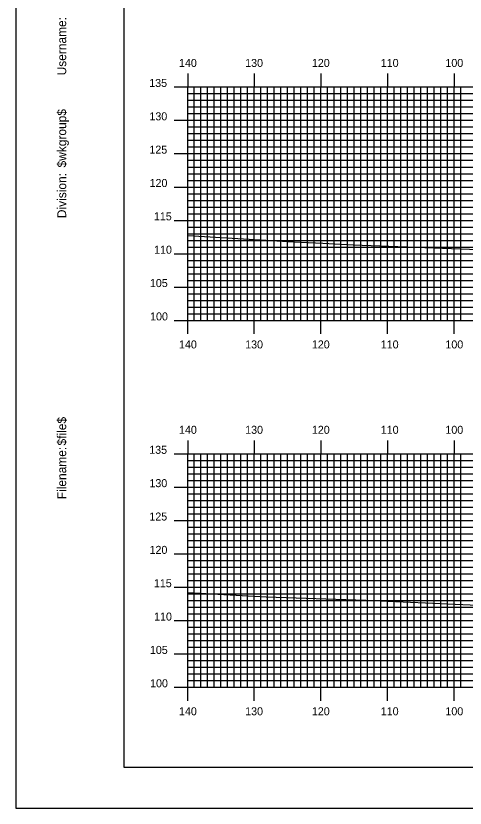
# Model space of a CAD drawing. Extents: x 1781467 to 1781810, y 442591 to 442811.
# Drawn here: x 1781466.6 to 1781534.1, y 442590.5 to 442709.3 of the extents above; entities that cross this region are included whole.
import ezdxf

# ---------------------------------------------------------------- set-up
doc = ezdxf.new("R2010")
doc.units = 0
for name, color, linetype in [('BORDER', 7, 'Continuous'), ('H_V ANNOTATION', 7, 'Continuous'), ('MAJOR', 7, 'Continuous'), ('MINOR', 7, 'Continuous'), ('PLOT BOUNDARY', 7, 'Continuous'), ('S_Roadway_Centerline', 7, 'Continuous')]:
    doc.layers.add(name, color=color, linetype=linetype)

msp = doc.modelspace()

# ---------------------------------------------------------------- linework, layer by layer
at = {"layer": 'BORDER'}
msp.add_lwpolyline([(1781482.81, 442596.67), (1781802.81, 442596.67), (1781802.81, 442806.67), (1781482.81, 442806.67)], close=True, dxfattribs=at)
at = {"layer": 'MAJOR'}
for p, q in [((1781492.41, 442700.67), (1781492.41, 442698.67)), ((1781502.41, 442700.67), (1781502.41, 442698.67)), ((1781512.41, 442700.67), (1781512.41, 442698.67)), ((1781522.41, 442700.67), (1781522.41, 442698.67)), ((1781532.41, 442700.67), (1781532.41, 442698.67)), ((1781490.4, 442698.67), (1781492.41, 442698.67)), ((1781492.41, 442698.67), (1781772.41, 442698.67)), ((1781492.41, 442663.67), (1781492.41, 442698.67)), ((1781492.41, 442663.67), (1781492.41, 442698.67)), ((1781492.41, 442698.67), (1781772.41, 442698.67)), ((1781502.41, 442663.67), (1781502.41, 442698.67)), ((1781512.41, 442663.67), (1781512.41, 442698.67)), ((1781522.41, 442663.67), (1781522.41, 442698.67)), ((1781532.41, 442663.67), (1781532.41, 442698.67)), ((1781490.4, 442693.67), (1781492.41, 442693.67)), ((1781492.41, 442693.67), (1781772.41, 442693.67)), ((1781490.4, 442688.67), (1781492.41, 442688.67)), ((1781492.41, 442688.67), (1781772.41, 442688.67)), ((1781490.4, 442683.67), (1781492.41, 442683.67)), ((1781492.41, 442683.67), (1781772.41, 442683.67)), ((1781490.4, 442678.67), (1781492.41, 442678.67)), ((1781492.41, 442678.67), (1781772.41, 442678.67)), ((1781490.4, 442673.67), (1781492.41, 442673.67)), ((1781492.41, 442673.67), (1781772.41, 442673.67)), ((1781490.4, 442668.67), (1781492.41, 442668.67)), ((1781492.41, 442668.67), (1781772.41, 442668.67)), ((1781490.4, 442663.67), (1781492.41, 442663.67)), ((1781492.41, 442663.67), (1781772.41, 442663.67)), ((1781492.41, 442663.67), (1781772.41, 442663.67)), ((1781492.41, 442661.66), (1781492.41, 442663.67)), ((1781502.41, 442661.66), (1781502.41, 442663.67)), ((1781512.41, 442661.66), (1781512.41, 442663.67)), ((1781522.41, 442661.66), (1781522.41, 442663.67)), ((1781532.41, 442661.66), (1781532.41, 442663.67)), ((1781492.41, 442645.67), (1781492.41, 442643.67)), ((1781502.41, 442645.67), (1781502.41, 442643.67)), ((1781512.41, 442645.67), (1781512.41, 442643.67)), ((1781522.41, 442645.67), (1781522.41, 442643.67)), ((1781532.41, 442645.67), (1781532.41, 442643.67)), ((1781490.4, 442643.67), (1781492.41, 442643.67)), ((1781492.41, 442643.67), (1781772.41, 442643.67)), ((1781492.41, 442608.67), (1781492.41, 442643.67)), ((1781492.41, 442608.67), (1781492.41, 442643.67)), ((1781492.41, 442643.67), (1781772.41, 442643.67)), ((1781502.41, 442608.67), (1781502.41, 442643.67)), ((1781512.41, 442608.67), (1781512.41, 442643.67)), ((1781522.41, 442608.67), (1781522.41, 442643.67)), ((1781532.41, 442608.67), (1781532.41, 442643.67)), ((1781490.4, 442638.67), (1781492.41, 442638.67)), ((1781492.41, 442638.67), (1781772.41, 442638.67)), ((1781490.4, 442633.67), (1781492.41, 442633.67)), ((1781492.41, 442633.67), (1781772.41, 442633.67)), ((1781490.4, 442628.67), (1781492.41, 442628.67)), ((1781492.41, 442628.67), (1781772.41, 442628.67)), ((1781490.4, 442623.67), (1781492.41, 442623.67)), ((1781492.41, 442623.67), (1781772.41, 442623.67)), ((1781490.4, 442618.67), (1781492.41, 442618.67)), ((1781492.41, 442618.67), (1781772.41, 442618.67)), ((1781490.4, 442613.67), (1781492.41, 442613.67)), ((1781492.41, 442613.67), (1781772.41, 442613.67)), ((1781490.4, 442608.67), (1781492.41, 442608.67)), ((1781492.41, 442608.67), (1781772.41, 442608.67)), ((1781492.41, 442608.67), (1781772.41, 442608.67)), ((1781492.41, 442606.66), (1781492.41, 442608.67)), ((1781502.41, 442606.66), (1781502.41, 442608.67)), ((1781512.41, 442606.66), (1781512.41, 442608.67)), ((1781522.41, 442606.66), (1781522.41, 442608.67)), ((1781532.41, 442606.66), (1781532.41, 442608.67))]:
    msp.add_line(p, q, dxfattribs=at)
at = {"layer": 'MINOR'}
for p, q in [((1781493.41, 442663.67), (1781493.41, 442698.67)), ((1781494.41, 442663.67), (1781494.41, 442698.67)), ((1781495.41, 442663.67), (1781495.41, 442698.67)), ((1781496.41, 442663.67), (1781496.41, 442698.67)), ((1781497.41, 442663.67), (1781497.41, 442698.67)), ((1781498.41, 442663.67), (1781498.41, 442698.67)), ((1781499.41, 442663.67), (1781499.41, 442698.67)), ((1781500.41, 442663.67), (1781500.41, 442698.67)), ((1781501.41, 442663.67), (1781501.41, 442698.67)), ((1781503.41, 442663.67), (1781503.41, 442698.67)), ((1781504.41, 442663.67), (1781504.41, 442698.67)), ((1781505.41, 442663.67), (1781505.41, 442698.67)), ((1781506.41, 442663.67), (1781506.41, 442698.67)), ((1781507.41, 442663.67), (1781507.41, 442698.67)), ((1781508.41, 442663.67), (1781508.41, 442698.67)), ((1781509.41, 442663.67), (1781509.41, 442698.67)), ((1781510.41, 442663.67), (1781510.41, 442698.67)), ((1781511.41, 442663.67), (1781511.41, 442698.67)), ((1781513.41, 442663.67), (1781513.41, 442698.67)), ((1781514.41, 442663.67), (1781514.41, 442698.67)), ((1781515.41, 442663.67), (1781515.41, 442698.67)), ((1781516.41, 442663.67), (1781516.41, 442698.67)), ((1781517.41, 442663.67), (1781517.41, 442698.67)), ((1781518.41, 442663.67), (1781518.41, 442698.67)), ((1781519.41, 442663.67), (1781519.41, 442698.67)), ((1781520.41, 442663.67), (1781520.41, 442698.67)), ((1781521.41, 442663.67), (1781521.41, 442698.67)), ((1781523.41, 442663.67), (1781523.41, 442698.67)), ((1781524.41, 442663.67), (1781524.41, 442698.67)), ((1781525.41, 442663.67), (1781525.41, 442698.67)), ((1781526.41, 442663.67), (1781526.41, 442698.67)), ((1781527.41, 442663.67), (1781527.41, 442698.67)), ((1781528.41, 442663.67), (1781528.41, 442698.67)), ((1781529.41, 442663.67), (1781529.41, 442698.67)), ((1781530.41, 442663.67), (1781530.41, 442698.67)), ((1781531.41, 442663.67), (1781531.41, 442698.67)), ((1781533.41, 442663.67), (1781533.41, 442698.67)), ((1781492.41, 442697.67), (1781772.41, 442697.67)), ((1781492.41, 442697.67), (1781494.41, 442697.67)), ((1781492.41, 442696.67), (1781772.41, 442696.67)), ((1781492.41, 442696.67), (1781494.41, 442696.67)), ((1781492.41, 442695.67), (1781772.41, 442695.67)), ((1781492.41, 442695.67), (1781494.41, 442695.67)), ((1781492.41, 442694.67), (1781772.41, 442694.67)), ((1781492.41, 442694.67), (1781494.41, 442694.67)), ((1781492.41, 442692.67), (1781772.41, 442692.67)), ((1781492.41, 442692.67), (1781494.41, 442692.67)), ((1781492.41, 442691.67), (1781772.41, 442691.67)), ((1781492.41, 442691.67), (1781494.41, 442691.67)), ((1781492.41, 442690.67), (1781772.41, 442690.67)), ((1781492.41, 442690.67), (1781494.41, 442690.67)), ((1781492.41, 442689.67), (1781772.41, 442689.67)), ((1781492.41, 442689.67), (1781494.41, 442689.67)), ((1781492.41, 442687.67), (1781772.41, 442687.67)), ((1781492.41, 442687.67), (1781494.41, 442687.67)), ((1781492.41, 442686.67), (1781772.41, 442686.67)), ((1781492.41, 442686.67), (1781494.41, 442686.67)), ((1781492.41, 442685.67), (1781772.41, 442685.67)), ((1781492.41, 442685.67), (1781494.41, 442685.67)), ((1781492.41, 442684.67), (1781772.41, 442684.67)), ((1781492.41, 442684.67), (1781494.41, 442684.67)), ((1781492.41, 442682.67), (1781772.41, 442682.67)), ((1781492.41, 442682.67), (1781494.41, 442682.67)), ((1781492.41, 442681.67), (1781772.41, 442681.67)), ((1781492.41, 442681.67), (1781494.41, 442681.67)), ((1781492.41, 442680.67), (1781772.41, 442680.67)), ((1781492.41, 442680.67), (1781494.41, 442680.67)), ((1781492.41, 442679.67), (1781772.41, 442679.67)), ((1781492.41, 442679.67), (1781494.41, 442679.67)), ((1781492.41, 442677.67), (1781772.41, 442677.67)), ((1781492.41, 442677.67), (1781494.41, 442677.67)), ((1781492.41, 442676.67), (1781772.41, 442676.67)), ((1781492.41, 442676.67), (1781494.41, 442676.67)), ((1781492.41, 442675.67), (1781772.41, 442675.67)), ((1781492.41, 442675.67), (1781494.41, 442675.67)), ((1781492.41, 442674.67), (1781772.41, 442674.67)), ((1781492.41, 442674.67), (1781494.41, 442674.67)), ((1781492.41, 442672.67), (1781772.41, 442672.67)), ((1781492.41, 442672.67), (1781494.41, 442672.67)), ((1781492.41, 442671.67), (1781772.41, 442671.67)), ((1781492.41, 442671.67), (1781494.41, 442671.67)), ((1781492.41, 442670.67), (1781772.41, 442670.67)), ((1781492.41, 442670.67), (1781494.41, 442670.67)), ((1781492.41, 442669.67), (1781772.41, 442669.67)), ((1781492.41, 442669.67), (1781494.41, 442669.67)), ((1781492.41, 442667.67), (1781772.41, 442667.67)), ((1781492.41, 442667.67), (1781494.41, 442667.67)), ((1781492.41, 442666.67), (1781772.41, 442666.67)), ((1781492.41, 442666.67), (1781494.41, 442666.67)), ((1781492.41, 442665.67), (1781772.41, 442665.67)), ((1781492.41, 442665.67), (1781494.41, 442665.67)), ((1781492.41, 442664.67), (1781772.41, 442664.67)), ((1781492.41, 442664.67), (1781494.41, 442664.67)), ((1781493.41, 442608.67), (1781493.41, 442643.67)), ((1781494.41, 442608.67), (1781494.41, 442643.67)), ((1781495.41, 442608.67), (1781495.41, 442643.67)), ((1781496.41, 442608.67), (1781496.41, 442643.67)), ((1781497.41, 442608.67), (1781497.41, 442643.67)), ((1781498.41, 442608.67), (1781498.41, 442643.67)), ((1781499.41, 442608.67), (1781499.41, 442643.67)), ((1781500.41, 442608.67), (1781500.41, 442643.67)), ((1781501.41, 442608.67), (1781501.41, 442643.67)), ((1781503.41, 442608.67), (1781503.41, 442643.67)), ((1781504.41, 442608.67), (1781504.41, 442643.67)), ((1781505.41, 442608.67), (1781505.41, 442643.67)), ((1781506.41, 442608.67), (1781506.41, 442643.67)), ((1781507.41, 442608.67), (1781507.41, 442643.67)), ((1781508.41, 442608.67), (1781508.41, 442643.67)), ((1781509.41, 442608.67), (1781509.41, 442643.67)), ((1781510.41, 442608.67), (1781510.41, 442643.67)), ((1781511.41, 442608.67), (1781511.41, 442643.67)), ((1781513.41, 442608.67), (1781513.41, 442643.67)), ((1781514.41, 442608.67), (1781514.41, 442643.67)), ((1781515.41, 442608.67), (1781515.41, 442643.67)), ((1781516.41, 442608.67), (1781516.41, 442643.67)), ((1781517.41, 442608.67), (1781517.41, 442643.67)), ((1781518.41, 442608.67), (1781518.41, 442643.67)), ((1781519.41, 442608.67), (1781519.41, 442643.67)), ((1781520.41, 442608.67), (1781520.41, 442643.67)), ((1781521.41, 442608.67), (1781521.41, 442643.67)), ((1781523.41, 442608.67), (1781523.41, 442643.67)), ((1781524.41, 442608.67), (1781524.41, 442643.67)), ((1781525.41, 442608.67), (1781525.41, 442643.67)), ((1781526.41, 442608.67), (1781526.41, 442643.67)), ((1781527.41, 442608.67), (1781527.41, 442643.67)), ((1781528.41, 442608.67), (1781528.41, 442643.67)), ((1781529.41, 442608.67), (1781529.41, 442643.67)), ((1781530.41, 442608.67), (1781530.41, 442643.67)), ((1781531.41, 442608.67), (1781531.41, 442643.67)), ((1781533.41, 442608.67), (1781533.41, 442643.67)), ((1781492.41, 442642.67), (1781772.41, 442642.67)), ((1781492.41, 442642.67), (1781494.41, 442642.67)), ((1781492.41, 442641.67), (1781772.41, 442641.67)), ((1781492.41, 442641.67), (1781494.41, 442641.67)), ((1781492.41, 442640.67), (1781772.41, 442640.67)), ((1781492.41, 442640.67), (1781494.41, 442640.67)), ((1781492.41, 442639.67), (1781772.41, 442639.67)), ((1781492.41, 442639.67), (1781494.41, 442639.67)), ((1781492.41, 442637.67), (1781772.41, 442637.67)), ((1781492.41, 442637.67), (1781494.41, 442637.67)), ((1781492.41, 442636.67), (1781772.41, 442636.67)), ((1781492.41, 442636.67), (1781494.41, 442636.67)), ((1781492.41, 442635.67), (1781772.41, 442635.67)), ((1781492.41, 442635.67), (1781494.41, 442635.67)), ((1781492.41, 442634.67), (1781772.41, 442634.67)), ((1781492.41, 442634.67), (1781494.41, 442634.67)), ((1781492.41, 442632.67), (1781772.41, 442632.67)), ((1781492.41, 442632.67), (1781494.41, 442632.67)), ((1781492.41, 442631.67), (1781772.41, 442631.67)), ((1781492.41, 442631.67), (1781494.41, 442631.67)), ((1781492.41, 442630.67), (1781772.41, 442630.67)), ((1781492.41, 442630.67), (1781494.41, 442630.67)), ((1781492.41, 442629.67), (1781772.41, 442629.67)), ((1781492.41, 442629.67), (1781494.41, 442629.67)), ((1781492.41, 442627.67), (1781772.41, 442627.67)), ((1781492.41, 442627.67), (1781494.41, 442627.67)), ((1781492.41, 442626.67), (1781772.41, 442626.67)), ((1781492.41, 442626.67), (1781494.41, 442626.67)), ((1781492.41, 442625.67), (1781772.41, 442625.67)), ((1781492.41, 442625.67), (1781494.41, 442625.67)), ((1781492.41, 442624.67), (1781772.41, 442624.67)), ((1781492.41, 442624.67), (1781494.41, 442624.67)), ((1781492.41, 442622.67), (1781772.41, 442622.67)), ((1781492.41, 442622.67), (1781494.41, 442622.67)), ((1781492.41, 442621.67), (1781772.41, 442621.67)), ((1781492.41, 442621.67), (1781494.41, 442621.67)), ((1781492.41, 442620.67), (1781772.41, 442620.67)), ((1781492.41, 442620.67), (1781494.41, 442620.67)), ((1781492.41, 442619.67), (1781772.41, 442619.67)), ((1781492.41, 442619.67), (1781494.41, 442619.67)), ((1781492.41, 442617.67), (1781772.41, 442617.67)), ((1781492.41, 442617.67), (1781494.41, 442617.67)), ((1781492.41, 442616.67), (1781772.41, 442616.67)), ((1781492.41, 442616.67), (1781494.41, 442616.67)), ((1781492.41, 442615.67), (1781772.41, 442615.67)), ((1781492.41, 442615.67), (1781494.41, 442615.67)), ((1781492.41, 442614.67), (1781772.41, 442614.67)), ((1781492.41, 442614.67), (1781494.41, 442614.67)), ((1781492.41, 442612.67), (1781772.41, 442612.67)), ((1781492.41, 442612.67), (1781494.41, 442612.67)), ((1781492.41, 442611.67), (1781772.41, 442611.67)), ((1781492.41, 442611.67), (1781494.41, 442611.67)), ((1781492.41, 442610.67), (1781772.41, 442610.67)), ((1781492.41, 442610.67), (1781494.41, 442610.67)), ((1781492.41, 442609.67), (1781772.41, 442609.67)), ((1781492.41, 442609.67), (1781494.41, 442609.67))]:
    msp.add_line(p, q, dxfattribs=at)
at = {"layer": 'PLOT BOUNDARY'}
msp.add_lwpolyline([(1781466.62, 442590.55), (1781806.62, 442590.55), (1781806.62, 442810.55), (1781466.62, 442810.55)], close=True, dxfattribs=at)
at = {"layer": 'S_Roadway_Centerline'}
for points in [[(1781492.41, 442676.39), (1781508.31, 442675.46), (1781512.71, 442675.23), (1781517.27, 442675), (1781532.01, 442674.45), (1781541.39, 442674.08), (1781554.26, 442673.54), (1781559.21, 442673.54), (1781577.11, 442673.04), (1781588.86, 442672.81), (1781593.64, 442672.55), (1781598.92, 442672.6), (1781605.77, 442672.68)], [(1781492.41, 442622.9), (1781504.21, 442622.23), (1781519.14, 442621.71), (1781534.81, 442621.02), (1781535.76, 442621), (1781536.77, 442620.96), (1781556.04, 442620.28), (1781557.67, 442620.21), (1781578.38, 442619.06), (1781580.48, 442618.97), (1781582.71, 442618.93), (1781593.57, 442618.68), (1781608.6, 442618.18)]]:
    msp.add_lwpolyline(points, dxfattribs=at)

# ---------------------------------------------------------------- texts
at = {"layer": 'BORDER'}
for s, p in [('Username:', (1781474.18, 442700.4)), ('$wkgroup$', (1781474.18, 442686.6)), ('Division:', (1781474.18, 442679)), ('$file$', (1781474.18, 442644.92)), ('Filename:', (1781474.18, 442636.86))]:
    msp.add_text(s, height=1.339, rotation=90, dxfattribs=at).set_placement(p)
at = {"layer": 'H_V ANNOTATION'}
for s, p in [('140', (1781491.11, 442701.67)), ('130', (1781501.04, 442701.67)), ('120', (1781511.05, 442701.67)), ('110', (1781521.39, 442701.67)), ('100', (1781531.09, 442701.67)), ('135', (1781486.64, 442698.67)), ('130', (1781486.67, 442693.67)), ('125', (1781486.66, 442688.67)), ('120', (1781486.69, 442683.67)), ('115', (1781487.34, 442678.67)), ('110', (1781487.37, 442673.67)), ('105', (1781486.74, 442668.67)), ('100', (1781486.77, 442663.67)), ('140', (1781491.11, 442659.47)), ('130', (1781501.04, 442659.47)), ('120', (1781511.05, 442659.47)), ('110', (1781521.39, 442659.47)), ('100', (1781531.09, 442659.47)), ('140', (1781491.11, 442646.67)), ('130', (1781501.04, 442646.67)), ('120', (1781511.05, 442646.67)), ('110', (1781521.39, 442646.67)), ('100', (1781531.09, 442646.67)), ('135', (1781486.64, 442643.67)), ('130', (1781486.67, 442638.67)), ('125', (1781486.66, 442633.67)), ('120', (1781486.69, 442628.67)), ('115', (1781487.34, 442623.67)), ('110', (1781487.37, 442618.67)), ('105', (1781486.74, 442613.67)), ('100', (1781486.77, 442608.67)), ('140', (1781491.11, 442604.47)), ('130', (1781501.04, 442604.47)), ('120', (1781511.05, 442604.47)), ('110', (1781521.39, 442604.47)), ('100', (1781531.09, 442604.47))]:
    msp.add_text(s, height=1.2, dxfattribs=at).set_placement(p)
at = {"layer": 'MAJOR'}
for p in [(1781492.4, 442663.67), (1781492.4, 442608.67)]:
    msp.add_text('-', height=0.012, dxfattribs=at).set_placement(p)

doc.saveas('drawing.dxf')
